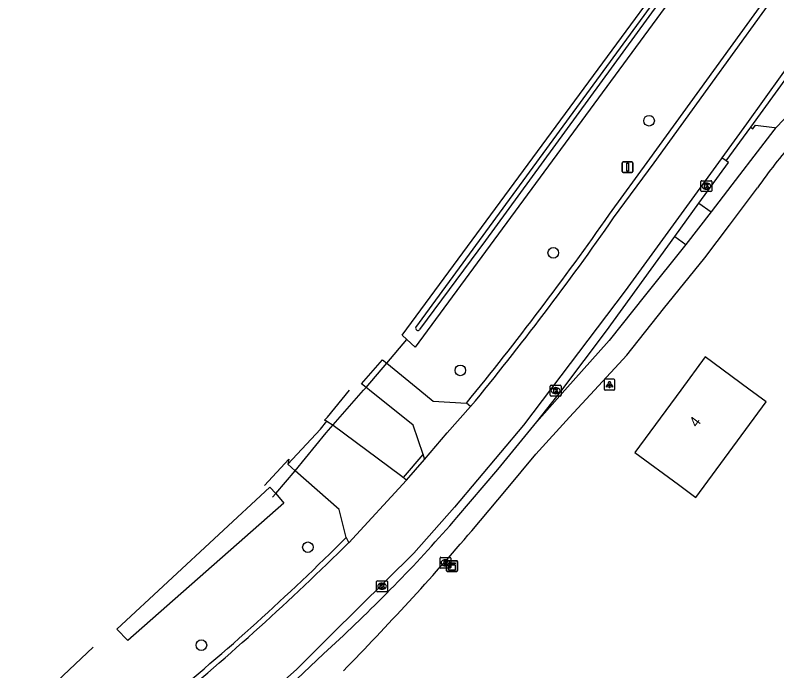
# Model space of a CAD drawing. Extents: x 152881 to 155736, y 382924 to 386919.
# Drawn here: x 152920.4 to 152990.7, y 384974.1 to 385034.6 of the extents above; entities that cross this region are included whole.
import ezdxf

# ---------------------------------------------------------------- set-up
doc = ezdxf.new("R2010")
doc.units = 0
for name, color, linetype in [('IMGEO_Boom', 7, 'Continuous'), ('IMGEO_Duiker', 7, 'Continuous'), ('IMGEO_Fietspad_gesloten', 7, 'Continuous'), ('IMGEO_Groenvoorziening', 7, 'Continuous'), ('IMGEO_Kast', 7, 'Continuous'), ('IMGEO_Kolk', 7, 'Continuous'), ('IMGEO_Lichtpunt', 7, 'Continuous'), ('IMGEO_Pand', 7, 'Continuous'), ('IMGEO_Pand_nummerreeks', 7, 'Continuous'), ('IMGEO_Rijbaan_lokaal_gesloten', 7, 'Continuous'), ('IMGEO_Rijbaan_lokaal_open', 7, 'Continuous'), ('IMGEO_Rioolput', 7, 'Continuous'), ('IMGEO_Verkeersbordpaal', 7, 'Continuous'), ('IMGEO_Waterloop', 7, 'Continuous')]:
    doc.layers.add(name, color=color, linetype=linetype)

msp = doc.modelspace()

# ---------------------------------------------------------------- linework, layer by layer
at = {"layer": 'IMGEO_Boom'}
for centre in [(152978.947, 385024.877), (152970.105, 385012.681), (152961.521, 385001.832), (152947.452, 384985.506), (152937.617, 384976.464)]:
    msp.add_circle(centre, 0.489, dxfattribs=at)
at = {"layer": 'IMGEO_Duiker'}
msp.add_lwpolyline([(152944.194, 384990.122), (152944.477, 384990.455), (152946.282, 384992.575), (152949.132, 384996.053), (152952.596, 385000), (152952.818, 385000.253), (152954.723, 385002.494), (152956.593, 385004.684)], dxfattribs=at)
at = {"layer": 'IMGEO_Fietspad_gesloten'}
for points in [[(152990.603, 385024.147), (152990.479, 385023.995), (152988.609, 385021.619), (152987.301, 385019.884), (152984.67, 385016.466)], [(152962.581, 384987.025), (152965.799, 384990.83), (152968.503, 384994.102), (152971.609, 384997.512), (152973.907, 385000), (152976.884, 385003.224), (152980.28, 385007.528), (152984.091, 385012.207), (152986.373, 385015.247), (152988.959, 385018.696)], [(152982.355, 385013.461), (152978.607, 385008.801), (152975.262, 385004.599), (152971.179, 385000), (152968.595, 384997.09)]]:
    msp.add_lwpolyline(points, dxfattribs=at)
for centre, radius, start, end in [((153032.46, 384988.095), 53.186, 139.04589, 144.87526), ((152770.156, 385151.69), 253.263, 315.47725, 319.44526)]:
    msp.add_arc(centre, radius, start, end, dxfattribs=at)
at = {"layer": 'IMGEO_Groenvoorziening'}
for points in [[(153000, 385062.004), (152957.362, 385003.989), (152956.593, 385004.684), (152956.145, 385005.088), (153000, 385064.614), (153059.575, 385146.646), (153070.728, 385162.004), (153072.139, 385161.169), (153060.903, 385145.723), (153000, 385062.004)], [(152948.981, 384997.226), (152949.063, 384997.318), (152949.251, 384997.529), (152951.298, 385000)], [(152943.451, 384991.193), (152945.693, 384993.638)], [(152920.433, 384969.493), (152927.085, 384975.764)], [(152927.085, 384975.764), (152927.084, 384975.763)], [(152927.085, 384975.764), (152927.62, 384976.268)]]:
    msp.add_lwpolyline(points, dxfattribs=at)
at = {"layer": 'IMGEO_Kast'}
for p, q in [((152960.257, 384983.341), (152960.257, 384984.182)), ((152960.257, 384984.182), (152960.257, 384983.341)), ((152960.332, 384984.266), (152961.173, 384984.266)), ((152961.173, 384984.266), (152960.332, 384984.266)), ((152961.257, 384984.191), (152961.257, 384983.35)), ((152961.257, 384983.35), (152961.257, 384984.191)), ((152961.182, 384983.266), (152960.341, 384983.266)), ((152960.341, 384983.266), (152961.182, 384983.266))]:
    msp.add_line(p, q, dxfattribs=at)
for points in [[(152960.452, 384984.056), (152961.052, 384984.056), (152961.052, 384983.971), (152960.452, 384983.971), (152960.452, 384984.056)], [(152960.452, 384983.881), (152961.052, 384983.881), (152961.052, 384983.392), (152960.452, 384983.392), (152960.452, 384983.881)]]:
    msp.add_lwpolyline(points, dxfattribs=at)
msp.add_circle((152960.536, 384983.73), 0.0377, dxfattribs=at)
for centre, start, end in [((152960.335, 384984.188), 92.4484, 184.28452), ((152960.335, 384984.188), 92.4484, 184.28452), ((152961.179, 384984.188), 2.4484, 94.28452), ((152961.179, 384984.188), 2.4484, 94.28452), ((152960.335, 384983.344), 182.4484, 274.28452), ((152960.335, 384983.344), 182.4484, 274.28452), ((152961.179, 384983.344), 272.4484, 4.28452), ((152961.179, 384983.344), 272.4484, 4.28452)]:
    msp.add_arc(centre, 0.0779, start, end, dxfattribs=at)
at = {"layer": 'IMGEO_Kolk'}
for p, q in [((152983.807, 385019.342), (152984.659, 385019.342)), ((152983.732, 385018.416), (152983.732, 385019.268)), ((152984.22, 385019.122), (152984.245, 385019.122)), ((152984.733, 385019.268), (152984.733, 385018.416)), ((152984.659, 385018.342), (152983.807, 385018.342)), ((152984.243, 385018.562), (152984.218, 385018.562)), ((152969.824, 384999.535), (152969.824, 385000.387)), ((152969.899, 385000.461), (152970.751, 385000.461)), ((152970.825, 385000.387), (152970.825, 384999.535)), ((152970.335, 384999.681), (152970.31, 384999.681)), ((152970.312, 385000.241), (152970.337, 385000.241)), ((152970.751, 384999.461), (152969.899, 384999.461)), ((152953.796, 384981.479), (152953.796, 384982.331)), ((152953.871, 384982.405), (152954.723, 384982.405)), ((152954.284, 384982.185), (152954.309, 384982.185)), ((152954.797, 384982.331), (152954.797, 384981.479)), ((152954.723, 384981.405), (152953.871, 384981.405)), ((152954.307, 384981.625), (152954.282, 384981.625))]:
    msp.add_line(p, q, dxfattribs=at)
for points in [[(152983.807, 385019.342), (152984.659, 385019.342)], [(152983.732, 385018.416), (152983.732, 385019.268)], [(152984.053, 385019.042), (152984.176, 385019.042), (152984.176, 385018.891), (152984.306, 385019.042), (152984.47, 385019.042), (152984.324, 385018.891), (152984.477, 385018.642), (152984.325, 385018.642), (152984.24, 385018.806), (152984.176, 385018.739), (152984.176, 385018.642), (152984.053, 385018.642), (152984.053, 385019.042)], [(152984.733, 385019.268), (152984.733, 385018.416)], [(152984.659, 385018.342), (152983.807, 385018.342)], [(152969.824, 384999.535), (152969.824, 385000.387)], [(152969.899, 385000.461), (152970.751, 385000.461)], [(152970.825, 385000.387), (152970.825, 384999.535)], [(152970.145, 385000.161), (152970.268, 385000.161), (152970.268, 385000.01), (152970.398, 385000.161), (152970.562, 385000.161), (152970.416, 385000.01), (152970.569, 384999.761), (152970.417, 384999.761), (152970.332, 384999.925), (152970.268, 384999.858), (152970.268, 384999.761), (152970.145, 384999.761), (152970.145, 385000.161)], [(152970.751, 384999.461), (152969.899, 384999.461)], [(152953.796, 384981.479), (152953.796, 384982.331)], [(152953.871, 384982.405), (152954.723, 384982.405)], [(152954.117, 384982.105), (152954.24, 384982.105), (152954.24, 384981.954), (152954.37, 384982.105), (152954.534, 384982.105), (152954.388, 384981.954), (152954.541, 384981.705), (152954.389, 384981.705), (152954.304, 384981.869), (152954.24, 384981.802), (152954.24, 384981.705), (152954.117, 384981.705), (152954.117, 384982.105)], [(152954.797, 384982.331), (152954.797, 384981.479)], [(152954.723, 384981.405), (152953.871, 384981.405)]]:
    msp.add_lwpolyline(points, dxfattribs=at)
for centre, start, end in [((152983.809, 385019.266), 91.55205, 178.44795), ((152983.809, 385019.266), 91.55205, 178.44795), ((152984.657, 385019.266), 1.55205, 88.44795), ((152984.657, 385019.266), 1.55205, 88.44795), ((152983.809, 385018.418), 181.55205, 268.44795), ((152983.809, 385018.418), 181.55205, 268.44795), ((152984.657, 385018.418), 271.55205, 358.44795), ((152984.657, 385018.418), 271.55205, 358.44795), ((152969.901, 385000.385), 91.55205, 178.44795), ((152969.901, 385000.385), 91.55205, 178.44795), ((152970.749, 385000.385), 1.55205, 88.44795), ((152970.749, 385000.385), 1.55205, 88.44795), ((152969.901, 384999.537), 181.55205, 268.44795), ((152969.901, 384999.537), 181.55205, 268.44795), ((152970.749, 384999.537), 271.55205, 358.44795), ((152970.749, 384999.537), 271.55205, 358.44795), ((152953.873, 384982.329), 91.55205, 178.44795), ((152953.873, 384982.329), 91.55205, 178.44795), ((152954.721, 384982.329), 1.55205, 88.44795), ((152954.721, 384982.329), 1.55205, 88.44795), ((152953.873, 384981.481), 181.55205, 268.44795), ((152953.873, 384981.481), 181.55205, 268.44795), ((152954.721, 384981.481), 271.55205, 358.44795), ((152954.721, 384981.481), 271.55205, 358.44795)]:
    msp.add_arc(centre, 0.0765, start, end, dxfattribs=at)
for centre, major_axis, ratio, start_param, end_param in [((152984.219, 385018.842), (-0.387, 0.002), 0.722429, 4.712389, 7.853982), ((152984.244, 385018.842), (-0.39, 0.002), 0.717154, 1.570796, 4.712389), ((152970.311, 384999.961), (-0.387, 0.002), 0.722429, 4.712389, 7.853982), ((152970.336, 384999.961), (-0.39, 0.002), 0.717154, 1.570796, 4.712389), ((152954.283, 384981.905), (-0.387, 0.002), 0.722429, 4.712389, 7.853982), ((152954.308, 384981.905), (-0.39, 0.002), 0.717154, 1.570796, 4.712389)]:
    msp.add_ellipse(centre, major_axis=major_axis, ratio=ratio, start_param=start_param, end_param=end_param, dxfattribs=at)
at = {"layer": 'IMGEO_Lichtpunt'}
for p, q in [((152974.795, 385000.923), (152974.795, 385000.116)), ((152974.795, 385000.923), (152974.795, 385000.116)), ((152975.697, 385001.018), (152974.889, 385001.018)), ((152975.697, 385001.018), (152974.889, 385001.018)), ((152975.791, 385000.116), (152975.791, 385000.923)), ((152975.791, 385000.116), (152975.791, 385000.923)), ((152974.889, 385000.022), (152975.697, 385000.022)), ((152974.889, 385000.022), (152975.697, 385000.022))]:
    msp.add_line(p, q, dxfattribs=at)
for points in [[(152975.169, 385000.587), (152975.208, 385000.559), (152975.02, 385000.297), (152974.982, 385000.324), (152975.169, 385000.587)], [(152975.271, 385000.539), (152975.318, 385000.539), (152975.318, 385000.217), (152975.271, 385000.217), (152975.271, 385000.539)], [(152975.381, 385000.559), (152975.419, 385000.586), (152975.606, 385000.324), (152975.567, 385000.296), (152975.381, 385000.559)]]:
    msp.add_lwpolyline(points, dxfattribs=at)
msp.add_circle((152975.294, 385000.721), 0.0994, dxfattribs=at)
for centre, start, end in [((152974.889, 385000.923), 90, 180), ((152974.889, 385000.923), 90, 180), ((152975.697, 385000.923), 0, 90), ((152975.697, 385000.923), 0, 90), ((152974.889, 385000.116), 180, 270), ((152974.889, 385000.116), 180, 270), ((152975.697, 385000.116), 270, 0), ((152975.697, 385000.116), 270, 360)]:
    msp.add_arc(centre, 0.0946, start, end, dxfattribs=at)
at = {"layer": 'IMGEO_Pand'}
msp.add_lwpolyline([(152988.162, 385000.103), (152984.139, 385003.071), (152981.874, 385000), (152977.64, 384994.26), (152981.663, 384991.292), (152983.273, 384990.104), (152989.755, 384998.927), (152988.162, 385000.103)], dxfattribs=at)
at = {"layer": 'IMGEO_Rijbaan_lokaal_gesloten'}
for points in [[(152975.289, 385016.238), (152979.03, 385021.373), (153018.922, 385076.461), (153077.758, 385157.409)], [(152975.677, 385015.906), (152979.411, 385020.996), (153019.311, 385076.151), (153066.926, 385141.651)], [(153070.761, 385138.878), (153023.094, 385073.275), (153005.301, 385048.581), (152991.207, 385029.157), (152987.933, 385024.584), (152985.658, 385021.458)], [(152988.337, 385024.29), (152991.769, 385029.005)], [(152986.067, 385021.169), (152988.337, 385024.29)], [(152985.658, 385021.458), (152985.588, 385021.361), (152976.729, 385009.189), (152967.34, 384996.77), (152960.992, 384989.193), (152957.232, 384984.967), (152949.587, 384977.419), (152946.43, 384974.266), (152937.222, 384966.042), (152931.359, 384961.408), (152921.577, 384953.958)], [(152986.067, 385021.169), (152986.05, 385021.181), (152985.658, 385021.458)], [(152958.204, 384993.613), (152960.294, 384996.073), (152962.476, 384998.501)], [(152962.476, 384998.501), (152962.103, 384998.815)], [(152956.275, 384991.932), (152958.085, 384994.055)], [(152958.085, 384994.055), (152958.098, 384994.018), (152958.204, 384993.613)], [(152956.56, 384991.699), (152958.204, 384993.613)], [(152956.56, 384991.699), (152956.443, 384991.794), (152956.275, 384991.932)], [(152951.215, 384985.911), (152956.56, 384991.699)], [(152950.985, 384986.404), (152951.215, 384985.911)]]:
    msp.add_lwpolyline(points, dxfattribs=at)
for centre, radius, start, end in [((152724.121, 385192.625), 306.917, 320.84104, 324.92094), ((152756.383, 385168.523), 267.174, 320.47814, 325.16412), ((152792.046, 385145.43), 224.836, 309.16045, 314.98437), ((152765.646, 385174.071), 264.272, 309.68816, 314.60274)]:
    msp.add_arc(centre, radius, start, end, dxfattribs=at)
at = {"layer": 'IMGEO_Rijbaan_lokaal_open'}
for points in [[(152990.603, 385024.147), (152993.152, 385026.798)], [(152988.337, 385024.29), (152988.536, 385024.145), (152988.776, 385024.477), (152990.521, 385024.245), (152990.603, 385024.147)], [(152983.553, 385017.266), (152986.274, 385021.023), (152986.067, 385021.169)], [(152981.333, 385014.199), (152983.553, 385017.266)], [(152983.553, 385017.266), (152984.67, 385016.466)], [(152984.67, 385016.466), (152982.355, 385013.461)], [(152968.595, 384997.09), (152970.886, 385000), (152975.013, 385005.472), (152981.333, 385014.199)], [(152981.333, 385014.199), (152982.355, 385013.461)], [(152958.085, 384994.055), (152957.163, 384996.764), (152953.133, 385000), (152952.818, 385000.253), (152952.403, 385000.59), (152954.331, 385002.814), (152954.723, 385002.494), (152957.779, 385000), (152959.003, 384999.001), (152962.103, 384998.815)], [(152945.603, 384993.175), (152948.615, 384996.418), (152949.201, 384997.134)], [(152949.201, 384997.134), (152948.981, 384997.226)], [(152949.201, 384997.134), (152949.77, 384996.78), (152956.007, 384992.151), (152956.275, 384991.932)], [(152961.215, 384988.254), (152964.984, 384992.697), (152968.595, 384997.09)], [(152945.693, 384993.638), (152945.603, 384993.175)], [(152945.693, 384993.638), (152945.693, 384993.638)], [(152950.985, 384986.404), (152950.337, 384988.994), (152946.282, 384992.575), (152945.603, 384993.175)], [(152945.824, 384972.748), (152948.903, 384975.656), (152949.991, 384976.683)]]:
    msp.add_lwpolyline(points, dxfattribs=at)
msp.add_arc((152849.838, 385085.062), 147.569, 312.74109, 319.00316, dxfattribs=at)
at = {"layer": 'IMGEO_Rioolput'}
for p, q in [((152959.648, 384983.649), (152959.648, 384984.501)), ((152959.723, 384984.575), (152960.575, 384984.575)), ((152960.136, 384984.355), (152960.161, 384984.355)), ((152960.649, 384984.501), (152960.649, 384983.649)), ((152960.575, 384983.575), (152959.723, 384983.575)), ((152960.159, 384983.795), (152960.134, 384983.795))]:
    msp.add_line(p, q, dxfattribs=at)
for points in [[(152959.648, 384983.649), (152959.648, 384984.501)], [(152959.723, 384984.575), (152960.575, 384984.575)], [(152960.237, 384984.273), (152959.985, 384984.275), (152959.985, 384983.875)], [(152960.163, 384984.194), (152960.109, 384984.194), (152960.109, 384984.113)], [(152960.649, 384984.501), (152960.649, 384983.649)], [(152960.575, 384983.575), (152959.723, 384983.575)], [(152959.985, 384983.875), (152960.109, 384983.875), (152960.109, 384984.037), (152960.12, 384984.037)], [(152960.109, 384984.113), (152960.161, 384984.113)], [(152960.167, 384984.008), (152960.238, 384983.875), (152960.378, 384983.875), (152960.313, 384984.001)]]:
    msp.add_lwpolyline(points, dxfattribs=at)
for centre, radius, start, end in [((152959.725, 384984.499), 0.0765, 91.55205, 178.44795), ((152959.725, 384984.499), 0.0765, 91.55205, 178.44795), ((152960.169, 384984.098), 0.0964, 77.00612, 93.18647), ((152960.183, 384984.155), 0.0378, 276.66336, 79.67722), ((152960.236, 384984.163), 0.109, 350.36119, 89.41601), ((152960.573, 384984.499), 0.0765, 1.55205, 88.44795), ((152960.573, 384984.499), 0.0765, 1.55205, 88.44795), ((152959.725, 384983.651), 0.0765, 181.55205, 268.44795), ((152959.725, 384983.651), 0.0765, 181.55205, 268.44795), ((152960.119, 384983.984), 0.0533, 26.02933, 88.69889), ((152960.145, 384984.302), 0.19, 274.7715, 282.96867), ((152960.234, 384984.163), 0.112, 277.58423, 350.98172), ((152960.218, 384983.948), 0.108, 29.51342, 73.79051), ((152960.573, 384983.651), 0.0765, 271.55205, 358.44795), ((152960.573, 384983.651), 0.0765, 271.55205, 358.44795)]:
    msp.add_arc(centre, radius, start, end, dxfattribs=at)
for centre, major_axis, ratio, start_param, end_param in [((152960.135, 384984.075), (-0.387, 0.002), 0.722429, 4.712389, 7.853982), ((152960.16, 384984.075), (-0.39, 0.002), 0.717154, 1.570796, 4.712389)]:
    msp.add_ellipse(centre, major_axis=major_axis, ratio=ratio, start_param=start_param, end_param=end_param, dxfattribs=at)
at = {"layer": 'IMGEO_Verkeersbordpaal'}
for p, q in [((152976.465, 385020.19), (152976.465, 385020.99)), ((152976.465, 385020.99), (152976.465, 385020.19)), ((152976.565, 385021.09), (152977.355, 385021.09)), ((152977.355, 385021.09), (152976.565, 385021.09)), ((152977.455, 385020.99), (152977.455, 385020.19)), ((152977.455, 385020.19), (152977.455, 385020.99)), ((152977.355, 385020.09), (152976.565, 385020.09)), ((152976.565, 385020.09), (152977.355, 385020.09))]:
    msp.add_line(p, q, dxfattribs=at)
msp.add_lwpolyline([(152976.885, 385020.965), (152977.035, 385020.965), (152977.035, 385020.215), (152976.885, 385020.215), (152976.885, 385020.965)], dxfattribs=at)
for centre, start, end in [((152976.565, 385020.99), 90, 180), ((152976.565, 385020.99), 90, 180), ((152977.355, 385020.99), 0, 90), ((152977.355, 385020.99), 360, 90), ((152976.565, 385020.19), 180, 270), ((152976.565, 385020.19), 180, 270), ((152977.355, 385020.19), 270, 0), ((152977.355, 385020.19), 270, 0)]:
    msp.add_arc(centre, 0.1, start, end, dxfattribs=at)
at = {"layer": 'IMGEO_Waterloop'}
for points in [[(152957.41, 385005.8), (153053.298, 385136.855), (153056.739, 385141.432), (153070.938, 385161.139)], [(153071.158, 385160.987), (153059.383, 385144.588), (153038.795, 385116.363), (153013.167, 385081.03), (152979.747, 385035.651), (152963.844, 385013.812), (152957.767, 385005.61)], [(152929.812, 384977.958), (152943.943, 384991.066), (152944.477, 384990.455), (152945.233, 384989.589), (152930.815, 384976.892), (152929.812, 384977.958)]]:
    msp.add_lwpolyline(points, dxfattribs=at)
msp.add_arc((152957.6, 385005.726), 0.204, 158.71989, 325.23514, dxfattribs=at)

# ---------------------------------------------------------------- texts
at = {"layer": 'IMGEO_Pand_nummerreeks'}
msp.add_text('4', height=1, rotation=53.58638, dxfattribs=at).set_placement((152983.366, 384996.498))

doc.saveas('drawing.dxf')
